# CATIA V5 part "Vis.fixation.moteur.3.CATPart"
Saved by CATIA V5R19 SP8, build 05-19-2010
Part number: Vis.fixation.moteur.3
Bounding box of the stored display mesh (mm): x -16.5 to -13.5, y -17 to -11, z -1.5 to 1.5
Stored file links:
  G:\EU_thinkMotion\CFAO_2010\MMS_groupe3\MMS_groupe3\jbonnamy\jbonnamy_cfao\Vis.fixation.moteur.3.CATPart
  C:\Users\Micheline\Desktop\projet CFAO\Nouveau dossier\temp\Nouveau dossier\Vis.fixation.CATPart
  G:\EU_thinkMotion\CFAO_2010\MMS_groupe3\MMS_groupe3\jbonnamy\jbonnamy_cfao\jbonnamy_suspension.arriere.directionnelle.CATProduct
  G:\EU_thinkMotion\CFAO_2010\MMS_groupe3\MMS_groupe3\jbonnamy\jbonnamy_cfao\Vis.fixation.moteur.2.CATPart
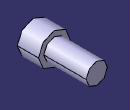
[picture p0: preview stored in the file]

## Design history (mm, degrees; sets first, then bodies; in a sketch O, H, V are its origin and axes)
External parameters (linked from other documents)
  External.Epaisseur.support.10 = 1.5 mm
  External.Diametre.vis.fixation = 2 mm
Set1
  DatumSurface1: linked copy from another document
Body1 (main body)
  Sketch1 on DatumSurface1, origin (-15, -15, 0), H (-1, 0, 0), V (0, 0, 1)
    circle A1 centre (0, 0) radius 1
    radius A1 = 1 {= External.Diametre.vis.fixation /2}
  Pad1: profile Sketch1, direction (0, 1, 0), length 4 {= 2*External.Epaisseur.support.10 +1mm}
  Sketch2 on DatumSurface1, origin (-15, -15, 0), H (-1, 0, 0), V (0, 0, 1)
    circle A1 centre (0, 0) radius 1.5
    radius A1 = 1.5 {= 3*External.Diametre.vis.fixation /4}
  Pad2: profile Sketch2, direction (0, -1, 0), length 2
